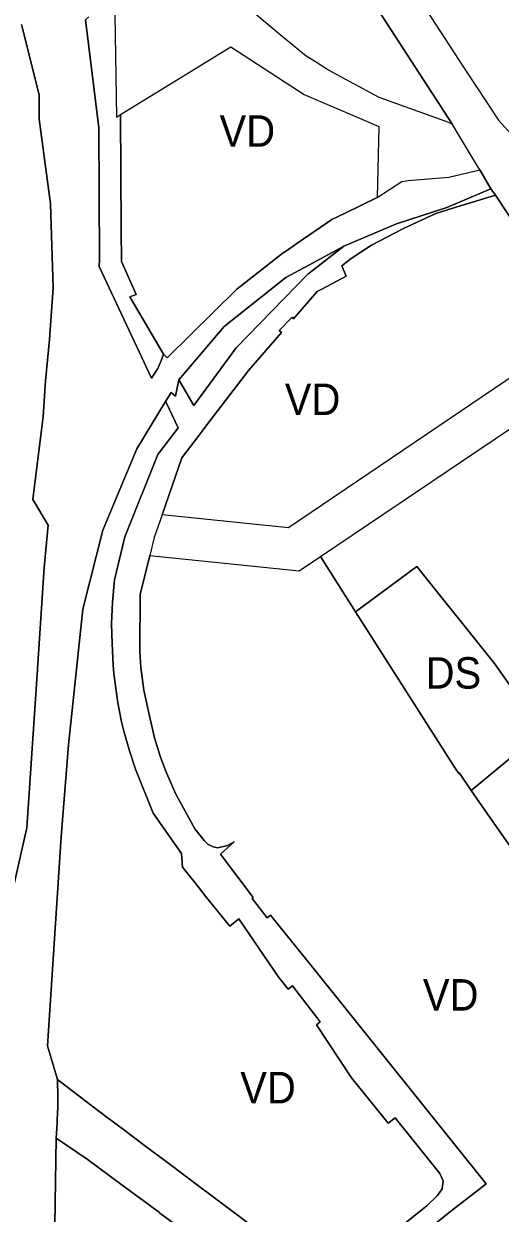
# Model space of a CAD drawing. Extents: x -650451 to -642268, y -1075216 to -1066610.
# Drawn here: x -647868.5 to -647686.8, y -1070274.4 to -1069820.3 of the extents above; entities that cross this region are included whole.
import ezdxf

# ---------------------------------------------------------------- set-up
doc = ezdxf.new("R2010")
doc.units = 0
doc.header["$LTSCALE"] = 4.8
for name, color, linetype, lineweight in [('1', 7, 'Continuous', 13), ('15', 7, 'Continuous', 13), ('2', 7, 'Continuous', 13), ('24', 7, 'Continuous', 13), ('25', 7, 'Continuous', 13), ('35', 7, 'Continuous', 13), ('40', 7, 'Continuous', 13)]:
    doc.layers.add(name, color=color, linetype=linetype, lineweight=lineweight)
doc.layers.add('62', color=7, linetype='Continuous')

msp = doc.modelspace()

# ---------------------------------------------------------------- linework, layer by layer
at = {"layer": '1'}
msp.add_line((-647755.356, -1070023.682), (-647645.274, -1069949.279), dxfattribs=at)
for points in [[(-647697.889, -1070112.941), (-647670.687, -1070090.426), (-647688.976, -1070064.453), (-647718.564, -1070027.479), (-647741.98, -1070044.74), (-647755.356, -1070023.682)], [(-647659.831, -1070167.317), (-647690.68, -1070123.43), (-647697.889, -1070112.941)]]:
    msp.add_lwpolyline(points, dxfattribs=at)
at = {"layer": '15'}
for points in [[(-647827.16, -1069795.32), (-647831.32, -1069806.56), (-647833.91, -1069808.91), (-647833.172, -1069855.944), (-647831.62, -1069854.99)], [(-647815.2, -1069946.41), (-647816.05, -1069948.55), (-647817.39, -1069951.94), (-647819.81, -1069955.62), (-647839.73, -1069913), (-647839.71, -1069910.43), (-647839.88, -1069860.04), (-647844.97, -1069818.73), (-647843.74, -1069817.63)], [(-647831.62, -1069854.99), (-647831.35, -1069898.79), (-647831.27, -1069911.02), (-647825.63, -1069923.6), (-647828.12, -1069924.51), (-647815.2, -1069946.41)], [(-647746.42, -1069905.22), (-647726.42, -1069896.7), (-647707.23, -1069890.37), (-647690.34, -1069883.26), (-647688.68, -1069885.74)], [(-647688.68, -1069885.74), (-647704.86, -1069890.66), (-647711.43, -1069892.66), (-647723.94, -1069898.6), (-647735.97, -1069904.81), (-647743.72, -1069909.85), (-647747.2, -1069912.7), (-647745.56, -1069916.62), (-647754.84, -1069921.56), (-647756.65, -1069922.52), (-647765.65, -1069932.9), (-647766.22, -1069932.35), (-647771.08, -1069937.39), (-647770.25, -1069938.2), (-647782.77, -1069952.63), (-647799.04, -1069973.95), (-647800.45, -1069975.8), (-647801.62, -1069977.33), (-647808.23, -1069985.99), (-647815.788, -1070007.72)], [(-647809.35, -1069956.2), (-647803.63, -1069966.05), (-647787.53, -1069944.06), (-647760.15, -1069915.82), (-647758.58, -1069914.6), (-647746.42, -1069905.22)], [(-647814.42, -1069964.48), (-647812.37, -1069961.12), (-647810.65, -1069962.44), (-647810, -1069959.31), (-647809.35, -1069956.2)], [(-647740.75, -1070292.28), (-647714.86, -1070271.59), (-647710.72, -1070267.61), (-647708.91, -1070265.11), (-647708.6, -1070262.04), (-647709.83, -1070259.21), (-647726.95, -1070237.9), (-647729.58, -1070240.01), (-647743.54, -1070222.69), (-647756.88, -1070202.41), (-647755.53, -1070201.33), (-647766.05, -1070187.51), (-647767.71, -1070188.83), (-647769.58, -1070186.48), (-647771.27, -1070184.36), (-647786.48, -1070161.98), (-647789.96, -1070164.75), (-647790.59, -1070163.97), (-647794.4, -1070159.28), (-647799.3, -1070153.27), (-647803.14, -1070148.21), (-647807.99, -1070142.22), (-647808.35, -1070137.04), (-647819.12, -1070121.67), (-647825.98, -1070104.82), (-647828.27, -1070097.88), (-647830.34, -1070090.34), (-647831.29, -1070086.72), (-647832.67, -1070079.47), (-647834.16, -1070068.39), (-647834.48, -1070065.12), (-647834.82, -1070056.91), (-647835.05, -1070049.32), (-647834.73, -1070041.12), (-647833.91, -1070032.61), (-647830.03, -1070016.17), (-647817.34, -1069984.77), (-647809.61, -1069974.57), (-647814.24, -1069964.86), (-647814.42, -1069964.48)], [(-647815.788, -1070007.72), (-647818.81, -1070016.41), (-647820.515, -1070023.319)], [(-647820.515, -1070023.319), (-647824.19, -1070038.21), (-647824.31, -1070059.98), (-647823.9, -1070066), (-647822.7, -1070074.66), (-647820.77, -1070084.03), (-647818.61, -1070092.95), (-647816.49, -1070099.89), (-647814.42, -1070105.36), (-647810.67, -1070114.2), (-647803.23, -1070127.57), (-647799.7, -1070132.06), (-647798.33, -1070133.44), (-647796.26, -1070134.52), (-647794.5, -1070134.85), (-647790.86, -1070133.97), (-647788.28, -1070132.65), (-647793.51, -1070137.3), (-647781.02, -1070153.88), (-647781.46, -1070154.2), (-647775.72, -1070161.6), (-647774.38, -1070160.53), (-647757.95, -1070181.04), (-647692.14, -1070263.17), (-647701.34, -1070270.29), (-647704.36, -1070272.63), (-647719.75, -1070284.93)]]:
    msp.add_lwpolyline(points, dxfattribs=at)
at = {"layer": '2'}
for points in [[(-647778.08, -1069746.18), (-647772.88, -1069754.18), (-647764.6, -1069766.94), (-647756.51, -1069779.4), (-647748.29, -1069792.07), (-647731.89, -1069817.33), (-647704.99, -1069858.7)], [(-647704.99, -1069858.7), (-647706.44, -1069857.98), (-647732.93, -1069848.5), (-647752.25, -1069837.95), (-647758.25, -1069834.21), (-647760.79, -1069832.61), (-647768.63, -1069826.34), (-647770.77, -1069824.47), (-647782.72, -1069814.46), (-647783.96, -1069813.49), (-647792.84, -1069803.65), (-647797.33, -1069798.65), (-647802.92, -1069792.37), (-647804.02, -1069791.01), (-647809.71, -1069782.79), (-647811.65, -1069780.12), (-647815.36, -1069774.66), (-647819.78, -1069765.84), (-647818.28, -1069764.99), (-647818.73, -1069763.53)], [(-647867.58, -1070459.6), (-647870.64, -1070433.56), (-647871.52, -1070421.5), (-647872.06, -1070408.04), (-647872.66, -1070398.77), (-647872.46, -1070392.48), (-647872.08, -1070375), (-647871.07, -1070358.52), (-647870.49, -1070342.22), (-647867.72, -1070323.46), (-647865.72, -1070321.45), (-647860.64, -1070318.32), (-647859.2, -1070309.44), (-647856.95, -1070295.54), (-647856.16, -1070245.75)], [(-647856.16, -1070245.75), (-647844.29, -1070253.79), (-647831.46, -1070263.23), (-647816.75, -1070274.06), (-647816.84, -1070274.2), (-647816.69, -1070274.34), (-647807.11, -1070281.38)]]:
    msp.add_lwpolyline(points, dxfattribs=at)
at = {"layer": '24'}
for points in [[(-647704.99, -1069858.7), (-647731.89, -1069817.33), (-647748.29, -1069792.07), (-647756.51, -1069779.4), (-647764.6, -1069766.94), (-647772.88, -1069754.18), (-647778.08, -1069746.18)], [(-647742.36, -1069746.93), (-647752.32, -1069752.95), (-647753.7, -1069753.9), (-647751.66, -1069757.12), (-647745.84, -1069766.71), (-647737.17, -1069780.85), (-647700.58, -1069837.2), (-647687.45, -1069857.15), (-647681.51, -1069863.72), (-647672.09, -1069878.85), (-647637.08, -1069934.31)], [(-647694.63, -1069876.07), (-647696.25, -1069873.35), (-647704.99, -1069858.7)], [(-647654.056, -1069935.903), (-647656.28, -1069932.53), (-647656.95, -1069933.03), (-647673.22, -1069908.91), (-647678.93, -1069900.35), (-647688.68, -1069885.74), (-647690.34, -1069883.26), (-647694.63, -1069876.07)], [(-647741.98, -1070044.74), (-647718.564, -1070027.479), (-647688.976, -1070064.453), (-647670.687, -1070090.426), (-647697.889, -1070112.941)], [(-647697.889, -1070112.941), (-647702.37, -1070106.42), (-647702.57, -1070106.56), (-647704.02, -1070104.5), (-647741.98, -1070044.74)], [(-647856.16, -1070245.75), (-647855.85, -1070240.02), (-647855.79, -1070238.86), (-647855.51, -1070233.65), (-647855.59, -1070230.08), (-647855.72, -1070223.34)], [(-647855.72, -1070223.34), (-647849.59, -1070228.06), (-647837.19, -1070237.39), (-647835.29, -1070238.81), (-647830.55, -1070242.37), (-647822.44, -1070248.47), (-647814.2, -1070254.66), (-647800.26, -1070265.15), (-647798.3, -1070266.62), (-647779.99, -1070280.38), (-647732.45, -1070316.12), (-647723.88, -1070322.56)], [(-647807.11, -1070281.38), (-647816.69, -1070274.34), (-647816.84, -1070274.2), (-647816.75, -1070274.06), (-647831.46, -1070263.23), (-647844.29, -1070253.79), (-647856.16, -1070245.75)]]:
    msp.add_lwpolyline(points, dxfattribs=at)
at = {"layer": '25'}
for points in [[(-647873.97, -1070156.58), (-647867.36, -1070127.21), (-647863.6, -1070070.49), (-647860.76, -1070027.86), (-647859.17, -1070011.72), (-647865.08, -1070001.86), (-647861.12, -1069970.21), (-647860.25, -1069956.63), (-647858.77, -1069940.78), (-647857.31, -1069921.08), (-647858.4, -1069889.05), (-647862.05, -1069861.48), (-647862.69, -1069856.72), (-647862.69, -1069847.43), (-647869.45, -1069820.63)], [(-647843.74, -1069817.63), (-647844.97, -1069818.73), (-647839.88, -1069860.04), (-647839.71, -1069910.43), (-647839.73, -1069913), (-647819.81, -1069955.62), (-647817.39, -1069951.94), (-647816.05, -1069948.55), (-647815.2, -1069946.41)], [(-647733.71, -1069886.65), (-647724.35, -1069880.48), (-647721.93, -1069880.14), (-647706.39, -1069878.81), (-647694.63, -1069876.07), (-647690.34, -1069883.26)], [(-647690.34, -1069883.26), (-647707.23, -1069890.37), (-647726.42, -1069896.7), (-647746.42, -1069905.22)], [(-647815.2, -1069946.41), (-647813.84, -1069947.8), (-647787.24, -1069921.59), (-647769.56, -1069907.76), (-647768.39, -1069906.95), (-647764.38, -1069904.18), (-647751.07, -1069894.98), (-647746.01, -1069892.54), (-647733.71, -1069886.65)], [(-647746.42, -1069905.22), (-647759.77, -1069912.39), (-647768.59, -1069917.13), (-647792.05, -1069935.92), (-647809.35, -1069956.2)], [(-647809.35, -1069956.2), (-647810, -1069959.31), (-647810.65, -1069962.44), (-647812.37, -1069961.12), (-647814.42, -1069964.48)], [(-647814.42, -1069964.48), (-647825.46, -1069982.61), (-647838.32, -1070013.63), (-647845.98, -1070043.72), (-647851.51, -1070095.53), (-647854.32, -1070130.73), (-647859.54, -1070210.41), (-647855.72, -1070223.34)], [(-647855.72, -1070223.34), (-647855.59, -1070230.08), (-647855.51, -1070233.65), (-647855.79, -1070238.86), (-647855.85, -1070240.02), (-647856.16, -1070245.75)], [(-647856.16, -1070245.75), (-647856.95, -1070295.54), (-647859.2, -1070309.44), (-647860.64, -1070318.32), (-647865.72, -1070321.45), (-647867.72, -1070323.46), (-647870.49, -1070342.22), (-647871.07, -1070358.52), (-647872.08, -1070375), (-647872.46, -1070392.48), (-647872.66, -1070398.77), (-647872.06, -1070408.04), (-647871.52, -1070421.5), (-647870.64, -1070433.56), (-647867.58, -1070459.6), (-647865.59, -1070470.14)]]:
    msp.add_lwpolyline(points, dxfattribs=at)
at = {"layer": '35'}
msp.add_line((-647831.62, -1069854.99), (-647789.55, -1069829.12), dxfattribs=at)
for points in [[(-647789.55, -1069829.12), (-647761.54, -1069847.24), (-647740.46, -1069856.29), (-647733.06, -1069859.46), (-647733.71, -1069886.65)], [(-647815.2, -1069946.41), (-647828.12, -1069924.51), (-647825.63, -1069923.6), (-647831.27, -1069911.02), (-647831.35, -1069898.79), (-647831.62, -1069854.99)], [(-647815.788, -1070007.72), (-647808.23, -1069985.99), (-647801.62, -1069977.33), (-647800.45, -1069975.8), (-647799.04, -1069973.95), (-647782.77, -1069952.63), (-647770.25, -1069938.2), (-647771.08, -1069937.39), (-647766.22, -1069932.35), (-647765.65, -1069932.9), (-647756.65, -1069922.52), (-647754.84, -1069921.56), (-647745.56, -1069916.62), (-647747.2, -1069912.7), (-647743.72, -1069909.85), (-647735.97, -1069904.81), (-647723.94, -1069898.6), (-647711.43, -1069892.66), (-647704.86, -1069890.66), (-647688.68, -1069885.74)], [(-647733.71, -1069886.65), (-647746.01, -1069892.54), (-647751.07, -1069894.98), (-647764.38, -1069904.18), (-647768.39, -1069906.95), (-647769.56, -1069907.76), (-647787.24, -1069921.59), (-647813.84, -1069947.8), (-647815.2, -1069946.41)], [(-647688.68, -1069885.74), (-647678.93, -1069900.35), (-647673.22, -1069908.91), (-647656.95, -1069933.03), (-647656.28, -1069932.53), (-647654.056, -1069935.903)], [(-647809.35, -1069956.2), (-647792.05, -1069935.92), (-647768.59, -1069917.13), (-647759.77, -1069912.39), (-647746.42, -1069905.22)], [(-647746.42, -1069905.22), (-647758.58, -1069914.6), (-647760.15, -1069915.82), (-647787.53, -1069944.06), (-647803.63, -1069966.05), (-647809.35, -1069956.2)], [(-647654.056, -1069935.903), (-647767.622, -1070012.66), (-647815.788, -1070007.72)], [(-647855.72, -1070223.34), (-647859.54, -1070210.41), (-647854.32, -1070130.73), (-647851.51, -1070095.53), (-647845.98, -1070043.72), (-647838.32, -1070013.63), (-647825.46, -1069982.61), (-647814.42, -1069964.48)], [(-647814.42, -1069964.48), (-647814.24, -1069964.86), (-647809.61, -1069974.57), (-647817.34, -1069984.77), (-647830.03, -1070016.17), (-647833.91, -1070032.61), (-647834.73, -1070041.12), (-647835.05, -1070049.32), (-647834.82, -1070056.91), (-647834.48, -1070065.12), (-647834.16, -1070068.39), (-647832.67, -1070079.47), (-647831.29, -1070086.72), (-647830.34, -1070090.34), (-647828.27, -1070097.88), (-647825.98, -1070104.82), (-647819.12, -1070121.67), (-647808.35, -1070137.04), (-647807.99, -1070142.22), (-647803.14, -1070148.21), (-647799.3, -1070153.27), (-647794.4, -1070159.28), (-647790.59, -1070163.97), (-647789.96, -1070164.75), (-647786.48, -1070161.98), (-647771.27, -1070184.36), (-647769.58, -1070186.48), (-647767.71, -1070188.83), (-647766.05, -1070187.51), (-647755.53, -1070201.33), (-647756.88, -1070202.41), (-647743.54, -1070222.69), (-647729.58, -1070240.01), (-647726.95, -1070237.9), (-647709.83, -1070259.21), (-647708.6, -1070262.04), (-647708.91, -1070265.11), (-647710.72, -1070267.61), (-647714.86, -1070271.59), (-647740.75, -1070292.28)], [(-647719.75, -1070284.93), (-647704.36, -1070272.63), (-647701.34, -1070270.29), (-647692.14, -1070263.17), (-647757.95, -1070181.04), (-647774.38, -1070160.53), (-647775.72, -1070161.6), (-647781.46, -1070154.2), (-647781.02, -1070153.88), (-647793.51, -1070137.3), (-647788.28, -1070132.65), (-647790.86, -1070133.97), (-647794.5, -1070134.85), (-647796.26, -1070134.52), (-647798.33, -1070133.44), (-647799.7, -1070132.06), (-647803.23, -1070127.57), (-647810.67, -1070114.2), (-647814.42, -1070105.36), (-647816.49, -1070099.89), (-647818.61, -1070092.95), (-647820.77, -1070084.03), (-647822.7, -1070074.66), (-647823.9, -1070066), (-647824.31, -1070059.98), (-647824.19, -1070038.21), (-647820.515, -1070023.319)], [(-647820.515, -1070023.319), (-647763.476, -1070029.17), (-647755.356, -1070023.682), (-647741.98, -1070044.74)], [(-647741.98, -1070044.74), (-647704.02, -1070104.5), (-647702.57, -1070106.56), (-647702.37, -1070106.42), (-647697.889, -1070112.941)], [(-647697.889, -1070112.941), (-647690.68, -1070123.43), (-647659.831, -1070167.317)], [(-647732.45, -1070316.12), (-647779.99, -1070280.38), (-647798.3, -1070266.62), (-647800.26, -1070265.15), (-647814.2, -1070254.66), (-647822.44, -1070248.47), (-647830.55, -1070242.37), (-647835.29, -1070238.81), (-647837.19, -1070237.39), (-647849.59, -1070228.06), (-647855.72, -1070223.34)]]:
    msp.add_lwpolyline(points, dxfattribs=at)
at = {"layer": '40'}
msp.add_lwpolyline([(-647869.45, -1069820.63), (-647862.69, -1069847.43), (-647862.69, -1069856.72), (-647862.05, -1069861.48), (-647858.4, -1069889.05), (-647857.31, -1069921.08), (-647858.77, -1069940.78), (-647860.25, -1069956.63), (-647861.12, -1069970.21), (-647865.08, -1070001.86), (-647859.17, -1070011.72), (-647860.76, -1070027.86), (-647863.6, -1070070.49), (-647867.36, -1070127.21), (-647873.97, -1070156.58), (-647902.17, -1070151.64)], dxfattribs=at)

# ---------------------------------------------------------------- texts
at = {"layer": '62', "width": 0.95}
for s, p in [('VD', (-647793.868, -1069867.222)), ('VD', (-647768.972, -1069969.65)), ('DS', (-647715.267, -1070074.101)), ('VD', (-647716.307, -1070197.014)), ('VD', (-647785.977, -1070232.424))]:
    msp.add_text(s, height=12, dxfattribs=at).set_placement(p)

doc.saveas('drawing.dxf')
